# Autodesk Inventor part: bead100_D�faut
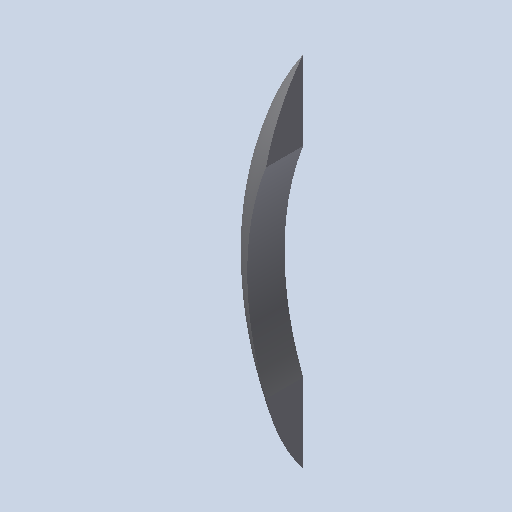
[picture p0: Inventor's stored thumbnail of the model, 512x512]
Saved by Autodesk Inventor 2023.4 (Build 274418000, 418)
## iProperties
Created: 2011-01
Part Number: bead100_D�faut
Document SubType Name: Modeling
Designer: eric
Density: 1 g/cm^3
Mass: 0.0354628 g
Surface Area: 1.11159 cm^2
Volume: 0.0354628 cm^3
Material: Générique
Appearance: Par défaut
Author: eric
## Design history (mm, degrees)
feature "Base1"
node "Corps solides"
node "Corps surfaciques"
node "Solide1"
